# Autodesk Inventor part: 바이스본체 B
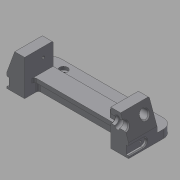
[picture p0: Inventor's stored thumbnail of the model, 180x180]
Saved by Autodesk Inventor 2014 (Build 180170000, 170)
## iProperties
Created: 2017-04
Part Number: 바이스본체 B
Material: 일반
Document SubType Name: Modeling
Designer: mduedu
Density: 1 g/cm^3
Appearance: 기본값
Mass: 119.615 g
Surface Area: 275.767 cm^2
Volume: 119.615 cm^3
Author: mduedu
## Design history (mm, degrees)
sketch "스케치1"
  geometry: L1 (-75, 0)-(75, 0); L2 (-75, 0)-(-75, 17); L3 (-53, 17)-(53, 17); L4 (75, 17)-(75, 0); L5 (-75, 17)-(-65.173, 44); L6 (-65.173, 44)-(-53, 44); L7 (-53, 44)-(-53, 17); L8 (0, 0)-(0, 17); L9 (75, 17)-(65.173, 44); L10 (65.173, 44)-(53, 44); L11 (53, 44)-(53, 17); 1 further point
  constraints: 22 end point, 4 perpendicular, 2 horizontal alignment, 2 midpoint, 2 symmetric about line, 1 coincident, 1 collinear, 1 horizontal, 1 vertical
  dimensions: "d0" = 150 distance of L1.start L1.end; "d1" = 17 distance of L1.start L2.end; "d2" = 27 distance of L3.start L6.end; "d3" = 22 distance of L3.start L2.end; "d4" = 70 deg angle of L3 L5; "d54" = 20 deg angle of L9 L4
extrude "돌출1" new body sketch "스케치1" stored distance "d5" = 70; taper "d6" = 0 deg
sketch "스케치2"
  geometry: L1 (0, 70)-(106, 70) reference; L2 (106, 70)-(106, 0) reference; L3 (106, 0)-(0, 0) reference; L4 (0, 47)-(106, 47); L5 (106, 47)-(106, 23); L6 (106, 23)-(0, 23); L7 (0, 23)-(0, 47); L8 (0, 70)-(0, 0) reference; 2 further points
  constraints: 8 end point, 2 parallel, 2 point on line, 1 horizontal, 1 horizontal alignment, 1 midpoint, 1 perpendicular
  dimensions: "d7" = 24 distance between parallel lines of L6 L4
extrude "돌출2" cut sketch "스케치2" stored distance "d9" = 70; taper "d10" = 0 deg
sketch "스케치3"
  geometry: L1 (22, -23)-(128, -23) reference; L2 (128, -47)-(22, -47) reference; L3 (22, -18)-(128, -18); L4 (128, -52)-(22, -52); L5 (22, -18)-(22, -52); L6 (128, -18)-(128, -52); 1 further point
  constraints: 8 end point, 3 parallel, 2 point on line, 1 perpendicular
  dimensions: "d11" = 5 distance between parallel lines of L3 L1; "d12" = 5 distance between parallel lines of L4 L2
extrude "돌출3" cut sketch "스케치3" distance "d13" = 12; taper "d14" = 0 deg
fillet "모깎기1" dims "d15" = 3, "d16" = 3
sketch "스케치4"
  geometry: L1 (103, 23)-(3, 23) reference; L2 (0, 26)-(0, 0) reference; L3 (106, 0)-(0, 0) reference; L4 (106, 26)-(106, 0) reference; L5 (96, 0)-(90, 0); L6 (90, 0)-(90, 19.5); L7 (96, 19.5)-(96, 0); L8 (90, 19.5)-(96, 19.5); A1 r 3 centre (3, 26) between (0, 26) and (3, 23) reference; A2 r 3 centre (103, 26) between (103, 23) and (106, 26) reference; 1 further point
  constraints: 8 end point, 2 perpendicular, 1 horizontal, 1 parallel, 1 point on line
  dimensions: "d17" = 10 distance between parallel lines of L7 L4; "d18" = 6 distance between parallel lines of L7 L6; "d27" = 3.5 distance between parallel lines of L8 L1
extrude "돌출4" join sketch "스케치4" distance "d19" = 12; taper "d20" = 0 deg
chamfer "모따기1" distance "d21" = 3; stored, may be unused: second distance "d22" = 2, angle "d23" = 45 deg
chamfer "모따기2" distance "d24" = 3; stored, may be unused: second distance "d25" = 2, angle "d26" = 45 deg
sketch "스케치5"
  geometry: L1 (-15.5, 35.8)-(-15.5, -25.8) reference; L2 (19.5, 0)-(0, 0) reference; C1 r 6.5 at (9.5, 15); 1 further point
  constraints: 1 centre point
  dimensions: "d28" = 13 diameter of C1; "d30" = 15 distance from line of C1.centre L2; "d31" = 25 distance from line of C1.centre L1
extrude "돌출5" cut sketch "스케치5" stored distance "d32" = 12; taper "d33" = 0 deg
sketch "스케치6"
  geometry: C1 r 5 at (-10, 15); C2 r 5 at (-60, 15); A1 r 6.5 centre (-10, 15) between (-15.766, 12) and (-4.234, 12) reference; A2 r 6.5 centre (-60, 15) between (-65.766, 12) and (-54.234, 12) reference; 1 further point
  constraints: 2 centre point, 2 coincident
  dimensions: "d34" = 10 diameter of C1; "d35" = 10 diameter of C2 (= d34)
extrude "돌출6" cut sketch "스케치6" stored distance "d36" = 12; taper "d37" = 0 deg
chamfer "모따기3" distance "d38" = 1; stored, may be unused: second distance "d39" = 2, angle "d40" = 45 deg
chamfer "모따기4" distance "d41" = 1; stored, may be unused: second distance "d42" = 2, angle "d43" = 45 deg
sketch "스케치7"
  geometry: L1 (-35, 35.8)-(-35, -25.8) reference; L2 (-70, 0)-(0, 0) reference; C1 r 5 at (-35, 15); 1 further point
  constraints: 1 centre point, 1 point on line
  dimensions: "d44" = 10 diameter of C1; "d45" = 15 distance from line of C1.centre L2
extrude "돌출7" cut sketch "스케치7" stored distance "d46" = 12; taper "d47" = 0 deg
chamfer "모따기5" distance "d48" = 1; stored, may be unused: second distance "d49" = 2, angle "d50" = 45 deg
node "작업축1"
sketch "스케치8"
  geometry: L1 (-105, 32)-(105, 32) reference; L2 (58, 32)-(64, 32); L3 (64, 32)-(64, 40); L4 (64, 40)-(58, 40); L5 (58, 40)-(58, 32); L6 (53, 38)-(53, 26) reference; 1 further point
  constraints: 8 end point, 2 parallel, 1 horizontal, 1 perpendicular, 1 point on line
  dimensions: "d51" = 5 distance from line of L6 L2.start; "d52" = 6 distance of L3.end L4.end; "d53" = 16 diameter of L4 L1
revolve "회전1" sketch "스케치8" stored, may be unused: angle "d55" = 90 deg
fillet "모깎기2"
chamfer "모따기6" distance "d56" = 1; stored, may be unused: second distance "d57" = 2, angle "d58" = 45 deg
sketch "스케치9"
  geometry: L1 (17.5, 3)-(52.5, 3); L2 (52.5, 13)-(17.5, 13); L3 (70, 0)-(0, 0) reference; L4 (17.5, 8)-(52.5, 8); A1 r 5 centre (17.5, 8) between (17.5, 13) and (17.5, 3); A2 r 5 centre (52.5, 8) between (52.5, 3) and (52.5, 13); 3 further points
  constraints: 6 end point, 4 point on circle, 3 tangent, 2 centre point, 2 midpoint, 2 parallel, 1 horizontal, 1 vertical alignment
  dimensions: "d59" = 35 distance of L4.start L4.end; "d61" = 5 radius of A2; "d62" = 8 distance between parallel lines of L3 L4
extrude "돌출8" cut sketch "스케치9" distance "d63" = 3; taper "d64" = 0 deg
chamfer "모따기7" distance "d65" = 1; stored, may be unused: second distance "d66" = 2, angle "d67" = 45 deg
chamfer "모따기8" distance "d68" = 1; stored, may be unused: second distance "d69" = 2, angle "d70" = 45 deg
feature "분할1"
sketch "스케치10"
  geometry: A1 r 5 centre (0, 0) between (0, 5) and (0, -5) reference; 1 further point
  constraints: 1 coincident
hole "구멍1" sketch "스케치10" at (0, 0) diameter "d71" = 2.459; stored, may be unused: countersink angle "d75" = 90 deg, drill point angle "d77" = 120 deg; dims "d72" = 4.5, "d73" = 4, "d74" = 2, "d76" = 6
sketch "스케치11"
  geometry: L1 (0, 0)-(0, 27) reference; L2 (0, 27)-(-35, 27) reference; 2 further points
  dimensions: "d78" = 12 distance from line of point (-12, 15.5) L1; "d79" = 11.5 distance from line of point (-12, 15.5) L2
hole "구멍2" sketch "스케치11" at (-12, 15.5) diameter "d80" = 3.242; stored, may be unused: countersink angle "d84" = 90 deg, drill point angle "d86" = 120 deg; dims "d81" = 6, "d82" = 4, "d83" = 2, "d85" = 8
sketch "스케치12"
  geometry: L1 (-75, -35)-(-75, 0) reference; L2 (75, -35)-(75, 0) reference; L3 (75, -35)-(-75, -35); L4 (-75, -35)-(-75, -55); L5 (-75, -55)-(75, -55); L6 (75, -55)-(75, -35); 1 further point
  constraints: 8 end point, 2 parallel, 1 horizontal, 1 perpendicular, 1 point on line
  dimensions: "d87" = 20 distance of L3.end L4.end; "d89" = 150 distance of L4.end L5.end (derived)
extrude "돌출9" join sketch "스케치12" distance "d90" = 10; taper "d91" = 0 deg
sketch "스케치13"
  geometry: L1 (-75, 55)-(-75, 35) reference; L2 (75, 35)-(75, 55) reference; L3 (-75, 45)-(75, 45); 3 further points
  constraints: 2 end point, 2 midpoint, 2 point on line
  dimensions: "d92" = 50 horizontal distance of point (-50, 45) point (0, 0); "d93" = 100 distance of point (50, 45) point (-50, 45)
fillet "모깎기3" dims "d94" = 12
chamfer "모따기9" distance "d95" = 1; stored, may be unused: second distance "d96" = 2, angle "d97" = 45 deg
hole "구멍3" sketch "스케치13" diameter "d98" = 4.134; stored, may be unused: countersink angle "d102" = 90 deg, drill point angle "d104" = 118 deg; dims "d99" = 6, "d100" = 10, "d101" = 4, "d103" = 8
node "솔리드1"
mirror "대칭1"
mirror "대칭2"
mirror "대칭3"
mirror "대칭4"
node "투영된 루프1"
